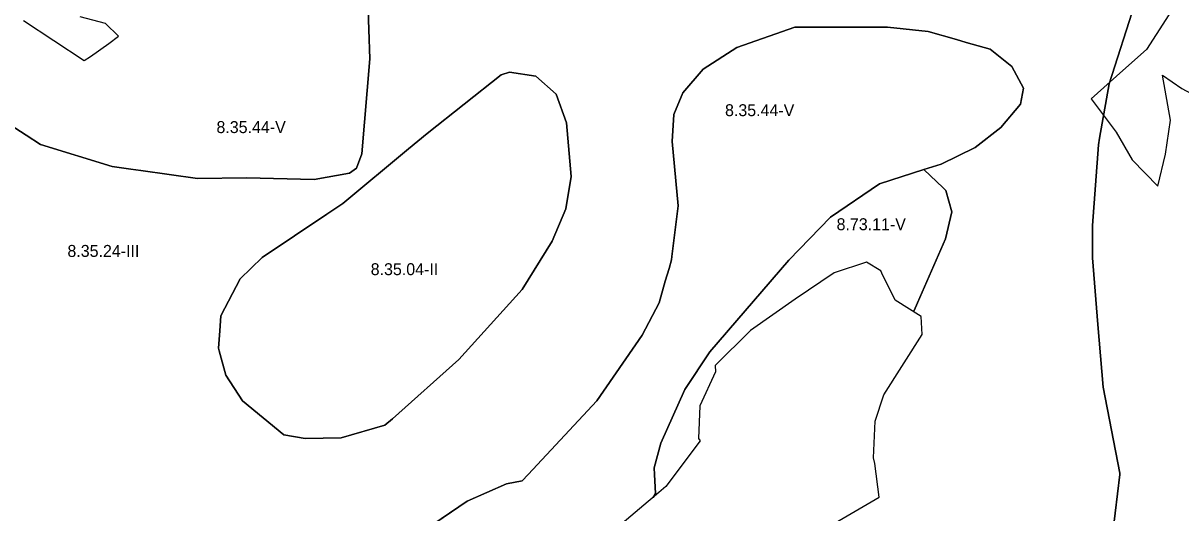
# Model space of a CAD drawing. Extents: x -547623 to -533936, y -1096714 to -1086523.
# Drawn here: x -543752 to -542784, y -1094032 to -1093623 of the extents above; entities that cross this region are included whole.
import ezdxf

# ---------------------------------------------------------------- set-up
doc = ezdxf.new("R2010")
doc.units = 0
for name, color, linetype in [('Vrstva 27', 7, 'Continuous'), ('Vrstva 28', 7, 'Continuous'), ('Vrstva 29', 7, 'Continuous')]:
    doc.layers.add(name, color=color, linetype=linetype)

msp = doc.modelspace()

# ---------------------------------------------------------------- linework, layer by layer
at = {"layer": 'Vrstva 28'}
for p, q in [((-543462.5, -1093652.5), (-543464, -1093603)), ((-543464, -1093603), (-543462.5, -1093652.5)), ((-542844, -1093673.5), (-542822.5, -1093606.5)), ((-542822.5, -1093606.5), (-542844, -1093673.5)), ((-543107, -1093626), (-543155.5, -1093643)), ((-543155.5, -1093643), (-543107, -1093626)), ((-543029.5, -1093626), (-543107, -1093626)), ((-543107, -1093626), (-543029.5, -1093626)), ((-542995.5, -1093629.5), (-543029.5, -1093626)), ((-543029.5, -1093626), (-542995.5, -1093629.5)), ((-542971.76, -1093636.35), (-542995.5, -1093629.5)), ((-542995.5, -1093629.5), (-542971.76, -1093636.35)), ((-542963.55, -1093638.72), (-542971.76, -1093636.35)), ((-542971.76, -1093636.35), (-542963.55, -1093638.72)), ((-543155.5, -1093643), (-543183.5, -1093661)), ((-543183.5, -1093661), (-543155.5, -1093643)), ((-542943.5, -1093644.5), (-542963.55, -1093638.72)), ((-542963.55, -1093638.72), (-542943.5, -1093644.5)), ((-542925.5, -1093659), (-542943.5, -1093644.5)), ((-542943.5, -1093644.5), (-542925.5, -1093659)), ((-543469, -1093732), (-543462.5, -1093652.5)), ((-543462.5, -1093652.5), (-543469, -1093732)), ((-543352.5, -1093666), (-543345.5, -1093663.5)), ((-543345.5, -1093663.5), (-543352.5, -1093666)), ((-543345.5, -1093663.5), (-543323.5, -1093667)), ((-543323.5, -1093667), (-543345.5, -1093663.5)), ((-543183.5, -1093661), (-543200.5, -1093681)), ((-543200.5, -1093681), (-543183.5, -1093661)), ((-542915.5, -1093677), (-542925.5, -1093659)), ((-542925.5, -1093659), (-542915.5, -1093677)), ((-543414.5, -1093715), (-543352.5, -1093666)), ((-543352.5, -1093666), (-543414.5, -1093715)), ((-543323.5, -1093667), (-543306.5, -1093682)), ((-543306.5, -1093682), (-543323.5, -1093667)), ((-542851.99, -1093718.78), (-542844, -1093673.5)), ((-542844, -1093673.5), (-542851.99, -1093718.78)), ((-543306.5, -1093682), (-543298, -1093706)), ((-543298, -1093706), (-543306.5, -1093682)), ((-543200.5, -1093681), (-543208, -1093699)), ((-543208, -1093699), (-543200.5, -1093681)), ((-542918, -1093690.5), (-542915.5, -1093677)), ((-542915.5, -1093677), (-542918, -1093690.5)), ((-542934.5, -1093710), (-542918, -1093690.5)), ((-542918, -1093690.5), (-542934.5, -1093710)), ((-543208, -1093699), (-543209.5, -1093721.5)), ((-543209.5, -1093721.5), (-543208, -1093699)), ((-543763.21, -1093707.8), (-543750, -1093716.28)), ((-543750, -1093716.28), (-543763.21, -1093707.8)), ((-543298, -1093706), (-543294, -1093751)), ((-543294, -1093751), (-543298, -1093706)), ((-542956, -1093726.5), (-542934.5, -1093710)), ((-542934.5, -1093710), (-542956, -1093726.5)), ((-543750, -1093716.28), (-543738, -1093724)), ((-543738, -1093724), (-543750, -1093716.28)), ((-543430.03, -1093727.89), (-543414.5, -1093715)), ((-543414.5, -1093715), (-543430.03, -1093727.89)), ((-543209.5, -1093721.5), (-543204.5, -1093775.5)), ((-543204.5, -1093775.5), (-543209.5, -1093721.5)), ((-542853, -1093724.5), (-542851.99, -1093718.78)), ((-542851.99, -1093718.78), (-542853, -1093724.5)), ((-543738, -1093724), (-543678, -1093742.5)), ((-543678, -1093742.5), (-543738, -1093724)), ((-543485, -1093773.5), (-543430.03, -1093727.89)), ((-543430.03, -1093727.89), (-543485, -1093773.5)), ((-543473.5, -1093744), (-543469, -1093732)), ((-543469, -1093732), (-543473.5, -1093744)), ((-542984.5, -1093740.5), (-542956, -1093726.5)), ((-542956, -1093726.5), (-542984.5, -1093740.5)), ((-542858, -1093792), (-542853, -1093724.5)), ((-542853, -1093724.5), (-542858, -1093792)), ((-543678, -1093742.5), (-543662.28, -1093744.7)), ((-543662.28, -1093744.7), (-543678, -1093742.5)), ((-542999, -1093745), (-542984.5, -1093740.5)), ((-542984.5, -1093740.5), (-542999, -1093745)), ((-543662.28, -1093744.7), (-543658.26, -1093745.26)), ((-543658.26, -1093745.26), (-543662.28, -1093744.7)), ((-543658.26, -1093745.26), (-543654, -1093745.86)), ((-543654, -1093745.86), (-543658.26, -1093745.26)), ((-543654, -1093745.86), (-543606.5, -1093752.5)), ((-543606.5, -1093752.5), (-543654, -1093745.86)), ((-543606.5, -1093752.5), (-543565.5, -1093752)), ((-543565.5, -1093752), (-543606.5, -1093752.5)), ((-543565.5, -1093752), (-543509, -1093753.5)), ((-543509, -1093753.5), (-543565.5, -1093752)), ((-543509, -1093753.5), (-543479.5, -1093748)), ((-543479.5, -1093748), (-543509, -1093753.5)), ((-543479.5, -1093748), (-543473.5, -1093744)), ((-543473.5, -1093744), (-543479.5, -1093748)), ((-543294, -1093751), (-543298.5, -1093778)), ((-543298.5, -1093778), (-543294, -1093751)), ((-542999, -1093745), (-543036, -1093757)), ((-543036, -1093757), (-542999, -1093745)), ((-542982.71, -1093760.41), (-542999, -1093745)), ((-542999, -1093745), (-542982.71, -1093760.41)), ((-543036, -1093757), (-543077, -1093785)), ((-543077, -1093785), (-543036, -1093757)), ((-542980.5, -1093762.5), (-542982.71, -1093760.41)), ((-542982.71, -1093760.41), (-542980.5, -1093762.5)), ((-542975.5, -1093780.5), (-542980.5, -1093762.5)), ((-542980.5, -1093762.5), (-542975.5, -1093780.5)), ((-543498.44, -1093782.46), (-543485, -1093773.5)), ((-543485, -1093773.5), (-543498.44, -1093782.46)), ((-543298.5, -1093778), (-543310, -1093805)), ((-543310, -1093805), (-543298.5, -1093778)), ((-543204.5, -1093775.5), (-543209.68, -1093817.9)), ((-543209.68, -1093817.9), (-543204.5, -1093775.5)), ((-542981, -1093803), (-542975.5, -1093780.5)), ((-542975.5, -1093780.5), (-542981, -1093803)), ((-543552.5, -1093818.5), (-543498.44, -1093782.46)), ((-543498.44, -1093782.46), (-543552.5, -1093818.5)), ((-543077, -1093785), (-543112, -1093821)), ((-543112, -1093821), (-543077, -1093785)), ((-542858, -1093819), (-542858, -1093792)), ((-542858, -1093792), (-542858, -1093819)), ((-543310, -1093805), (-543335, -1093845.5)), ((-543335, -1093845.5), (-543310, -1093805)), ((-543004.33, -1093856.66), (-542981, -1093803)), ((-542981, -1093803), (-543004.33, -1093856.66)), ((-543571, -1093836.5), (-543552.5, -1093818.5)), ((-543552.5, -1093818.5), (-543571, -1093836.5)), ((-543210, -1093820.5), (-543212.12, -1093827.76)), ((-543212.12, -1093827.76), (-543210, -1093820.5)), ((-543209.68, -1093817.9), (-543210, -1093820.5)), ((-543210, -1093820.5), (-543209.68, -1093817.9)), ((-542853.35, -1093874.79), (-542858, -1093819)), ((-542858, -1093819), (-542853.35, -1093874.79)), ((-543212.12, -1093827.76), (-543215.24, -1093838.48)), ((-543215.24, -1093838.48), (-543212.12, -1093827.76)), ((-543112, -1093821), (-543178, -1093897.5)), ((-543178, -1093897.5), (-543112, -1093821)), ((-543587, -1093867.5), (-543571, -1093836.5)), ((-543571, -1093836.5), (-543587, -1093867.5)), ((-543215.24, -1093838.48), (-543220.5, -1093856.5)), ((-543220.5, -1093856.5), (-543215.24, -1093838.48)), ((-543335, -1093845.5), (-543388, -1093904)), ((-543388, -1093904), (-543335, -1093845.5)), ((-543220.5, -1093856.5), (-543234.5, -1093883.5)), ((-543234.5, -1093883.5), (-543220.5, -1093856.5)), ((-543006.28, -1093861.15), (-543004.33, -1093856.66)), ((-543004.33, -1093856.66), (-543006.28, -1093861.15)), ((-543587.92, -1093879.93), (-543587, -1093867.5)), ((-543587, -1093867.5), (-543587.92, -1093879.93)), ((-543007.55, -1093864.07), (-543006.28, -1093861.15)), ((-543006.28, -1093861.15), (-543007.55, -1093864.07)), ((-542849, -1093927), (-542853.35, -1093874.79)), ((-542853.35, -1093874.79), (-542849, -1093927)), ((-543589, -1093894.5), (-543587.92, -1093879.93)), ((-543587.92, -1093879.93), (-543589, -1093894.5)), ((-543234.5, -1093883.5), (-543272.5, -1093938.5)), ((-543272.5, -1093938.5), (-543234.5, -1093883.5)), ((-543588.4, -1093896.73), (-543589, -1093894.5)), ((-543589, -1093894.5), (-543588.4, -1093896.73)), ((-543583, -1093917), (-543588.4, -1093896.73)), ((-543588.4, -1093896.73), (-543583, -1093917)), ((-543178, -1093897.5), (-543199, -1093929)), ((-543199, -1093929), (-543178, -1093897.5)), ((-543388, -1093904), (-543443.5, -1093953.5)), ((-543443.5, -1093953.5), (-543388, -1093904)), ((-543569, -1093938.5), (-543583, -1093917)), ((-543583, -1093917), (-543569, -1093938.5)), ((-542835, -1093999), (-542849, -1093927)), ((-542849, -1093927), (-542835, -1093999)), ((-543199, -1093929), (-543219, -1093974)), ((-543219, -1093974), (-543199, -1093929)), ((-543534.5, -1093967), (-543569, -1093938.5)), ((-543569, -1093938.5), (-543534.5, -1093967)), ((-543272.5, -1093938.5), (-543329.87, -1094000)), ((-543329.87, -1094000), (-543272.5, -1093938.5)), ((-543443.5, -1093953.5), (-543450, -1093959)), ((-543450, -1093959), (-543443.5, -1093953.5)), ((-543450, -1093959), (-543486.5, -1093969.5)), ((-543486.5, -1093969.5), (-543450, -1093959)), ((-543516.5, -1093970), (-543534.5, -1093967)), ((-543534.5, -1093967), (-543516.5, -1093970)), ((-543486.5, -1093969.5), (-543516.5, -1093970)), ((-543516.5, -1093970), (-543486.5, -1093969.5)), ((-543219, -1093974), (-543224.5, -1093994.5)), ((-543224.5, -1093994.5), (-543219, -1093974)), ((-543224.5, -1093994.5), (-543224.24, -1094000)), ((-543224.24, -1094000), (-543224.5, -1093994.5)), ((-543329.87, -1094000), (-543335, -1094005.5)), ((-543335, -1094005.5), (-543329.87, -1094000)), ((-543224.24, -1094000), (-543223.5, -1094016)), ((-543223.5, -1094016), (-543224.24, -1094000)), ((-542841, -1094048.5), (-542835.12, -1094000)), ((-542835.12, -1094000), (-542841, -1094048.5)), ((-542835.12, -1094000), (-542835, -1093999)), ((-542835, -1093999), (-542835.12, -1094000)), ((-543348, -1094008), (-543381, -1094022.5)), ((-543381, -1094022.5), (-543348, -1094008)), ((-543335, -1094005.5), (-543348, -1094008)), ((-543348, -1094008), (-543335, -1094005.5)), ((-543381, -1094022.5), (-543455, -1094072.5)), ((-543455, -1094072.5), (-543381, -1094022.5)), ((-543223.5, -1094016), (-543225.36, -1094019.23)), ((-543225.36, -1094019.23), (-543223.5, -1094016)), ((-543225.36, -1094019.23), (-543225.36, -1094019.23)), ((-543225.36, -1094019.23), (-543225.36, -1094019.23))]:
    msp.add_line(p, q, dxfattribs=at)
for points in [[(-543464, -1093603), (-543462.5, -1093652.5), (-543469, -1093732), (-543473.5, -1093744), (-543479.5, -1093748), (-543509, -1093753.5), (-543565.5, -1093752), (-543606.5, -1093752.5), (-543654, -1093745.86), (-543658.26, -1093745.26), (-543662.28, -1093744.7), (-543678, -1093742.5), (-543738, -1093724), (-543750, -1093716.28), (-543763.21, -1093707.8)], [(-542841, -1094048.5), (-542835.12, -1094000), (-542835, -1093999), (-542849, -1093927), (-542853.35, -1093874.79), (-542858, -1093819), (-542858, -1093792), (-542853, -1093724.5), (-542851.99, -1093718.78), (-542844, -1093673.5), (-542822.5, -1093606.5)], [(-543752.03, -1093620.49), (-543701.51, -1093653.95), (-543696.02, -1093650.54), (-543680.71, -1093639.69), (-543672.71, -1093633.55), (-543683.55, -1093623.02), (-543704.77, -1093617.4)], [(-543225.36, -1094019.23), (-543225.36, -1094019.23), (-543223.5, -1094016), (-543224.24, -1094000), (-543224.5, -1093994.5), (-543219, -1093974), (-543199, -1093929), (-543178, -1093897.5), (-543112, -1093821), (-543077, -1093785), (-543036, -1093757), (-542999, -1093745), (-542984.5, -1093740.5), (-542956, -1093726.5), (-542934.5, -1093710), (-542918, -1093690.5), (-542915.5, -1093677), (-542925.5, -1093659), (-542943.5, -1093644.5), (-542963.55, -1093638.72), (-542971.76, -1093636.35), (-542995.5, -1093629.5), (-543029.5, -1093626), (-543107, -1093626), (-543155.5, -1093643), (-543183.5, -1093661), (-543200.5, -1093681), (-543208, -1093699), (-543209.5, -1093721.5), (-543204.5, -1093775.5), (-543209.68, -1093817.9), (-543210, -1093820.5), (-543212.12, -1093827.76), (-543215.24, -1093838.48), (-543220.5, -1093856.5), (-543234.5, -1093883.5), (-543272.5, -1093938.5), (-543329.87, -1094000), (-543335, -1094005.5), (-543348, -1094008), (-543381, -1094022.5), (-543455, -1094072.5)], [(-543455, -1094072.5), (-543381, -1094022.5), (-543348, -1094008), (-543335, -1094005.5), (-543329.87, -1094000), (-543272.5, -1093938.5), (-543234.5, -1093883.5), (-543220.5, -1093856.5), (-543215.24, -1093838.48), (-543212.12, -1093827.76), (-543210, -1093820.5), (-543209.68, -1093817.9), (-543204.5, -1093775.5), (-543209.5, -1093721.5), (-543208, -1093699), (-543200.5, -1093681), (-543183.5, -1093661), (-543155.5, -1093643), (-543107, -1093626), (-543029.5, -1093626), (-542995.5, -1093629.5), (-542971.76, -1093636.35), (-542963.55, -1093638.72), (-542943.5, -1093644.5), (-542925.5, -1093659), (-542915.5, -1093677), (-542918, -1093690.5), (-542934.5, -1093710), (-542956, -1093726.5), (-542984.5, -1093740.5), (-542999, -1093745), (-542982.71, -1093760.41), (-542980.5, -1093762.5), (-542975.5, -1093780.5), (-542981, -1093803), (-543004.33, -1093856.66), (-543005.7, -1093859.8)], [(-543388, -1093904), (-543335, -1093845.5), (-543310, -1093805), (-543298.5, -1093778), (-543294, -1093751), (-543298, -1093706), (-543306.5, -1093682), (-543323.5, -1093667), (-543345.5, -1093663.5), (-543352.5, -1093666), (-543414.5, -1093715), (-543430.03, -1093727.89), (-543485, -1093773.5), (-543498.44, -1093782.46), (-543552.5, -1093818.5), (-543571, -1093836.5), (-543587, -1093867.5), (-543587.92, -1093879.93), (-543589, -1093894.5), (-543588.4, -1093896.73), (-543583, -1093917), (-543569, -1093938.5), (-543534.5, -1093967), (-543516.5, -1093970), (-543486.5, -1093969.5), (-543450, -1093959), (-543443.5, -1093953.5), (-543388, -1093904)], [(-543486.5, -1093969.5), (-543516.5, -1093970), (-543534.5, -1093967), (-543569, -1093938.5), (-543583, -1093917), (-543588.4, -1093896.73), (-543589, -1093894.5), (-543587.92, -1093879.93), (-543587, -1093867.5), (-543571, -1093836.5), (-543552.5, -1093818.5), (-543498.44, -1093782.46), (-543485, -1093773.5), (-543430.03, -1093727.89), (-543414.5, -1093715), (-543352.5, -1093666), (-543345.5, -1093663.5), (-543323.5, -1093667), (-543306.5, -1093682), (-543298, -1093706), (-543294, -1093751), (-543298.5, -1093778), (-543310, -1093805), (-543335, -1093845.5), (-543388, -1093904), (-543443.5, -1093953.5), (-543450, -1093959), (-543486.5, -1093969.5)], [(-543086.68, -1094048.41), (-543036.39, -1094019.02), (-543039.97, -1093991.04), (-543041.23, -1093986.06), (-543039.7, -1093955.61), (-543032.51, -1093933.48), (-543000.28, -1093883.04), (-543001.34, -1093867.93), (-543023, -1093854.45), (-543034.09, -1093831.74), (-543035.03, -1093829.81), (-543046.91, -1093822.48), (-543074.12, -1093831.6), (-543106.67, -1093853.47), (-543144.11, -1093879.7), (-543173.48, -1093908.91), (-543173.26, -1093914.37), (-543186.47, -1093942.62), (-543187.41, -1093970), (-543186.06, -1093971.89), (-543214.91, -1094010.07), (-543220.59, -1094015.21), (-543276.45, -1094062.24)]]:
    msp.add_lwpolyline(points, dxfattribs=at)
at = {"layer": 'Vrstva 29'}
msp.add_lwpolyline([(-542769.26, -1093663.94), (-542767.9, -1093639.76), (-542771.55, -1093614.52), (-542774.09, -1093574.55), (-542785.9, -1093602.97), (-542812.72, -1093644.61), (-542832.55, -1093662.16), (-542858.95, -1093685.92), (-542838.19, -1093713.79), (-542824.85, -1093737.01), (-542803.2, -1093759.09), (-542796.93, -1093732.12), (-542792.54, -1093703.66), (-542799.47, -1093666.28), (-542783.26, -1093677.26), (-542771.65, -1093683.4), (-542769.26, -1093663.94)], dxfattribs=at)

# ---------------------------------------------------------------- texts
at = {"layer": 'Vrstva 27'}
for s, p in [('8.35.44-V', (-543165.3, -1093700.43)), ('8.35.44-V', (-543590.73, -1093714.57)), ('8.73.11-V', (-543071.98, -1093795.81)), ('8.35.24-III', (-543715.4, -1093818.14)), ('8.35.04-II', (-543461.7, -1093833.41))]:
    msp.add_text(s, height=10, dxfattribs=at).set_placement(p)

doc.saveas('drawing.dxf')
